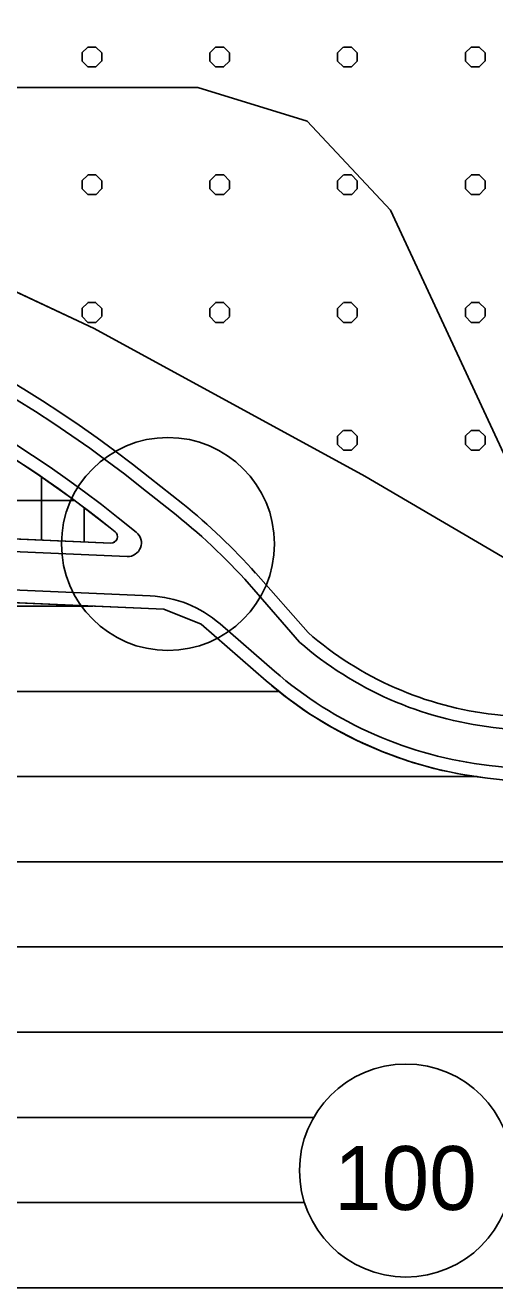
# Model space of a CAD drawing. Extents: x 427903 to 430077, y 4477233 to 4480385.
# Drawn here: x 429017.2 to 429127.4, y 4478826.8 to 4479123.1 of the extents above; entities that cross this region are included whole.
import ezdxf

# ---------------------------------------------------------------- set-up
doc = ezdxf.new("R2010")
doc.units = 0
for name, color, linetype in [('ADAKENARI', 7, 'Continuous'), ('KALDIRIM', 7, 'Continuous'), ('KD_KAV_DA', 7, 'Continuous'), ('PL_K_TALI_IS_MRK', 7, 'Continuous'), ('PL_KA_TARIM_OZEL', 7, 'Continuous'), ('PL_KON_ONE_100', 7, 'Continuous'), ('rezerv yapı alan', 7, 'Continuous'), ('SM_DAIRE', 7, 'Continuous'), ('SM_TAKS', 7, 'Continuous'), ('TR_AZYOGUNKONUT', 7, 'Continuous'), ('TR_OZELMAHSUL', 7, 'Continuous'), ('TR_TALIISMERK', 7, 'Continuous')]:
    doc.layers.add(name, color=color, linetype=linetype)

msp = doc.modelspace()

# ---------------------------------------------------------------- linework, layer by layer
at = {"layer": 'ADAKENARI'}
for p, q in [((428992.56, 4479071.13), (429033.41, 4479051.94)), ((429033.41, 4479051.94), (429096.95, 4479017.28)), ((429054.21, 4479010.76), (429046.48, 4479016.91)), ((429096.95, 4479017.28), (429125.65, 4479000.49)), ((429037.32, 4479001.59), (428951.02, 4479005.37)), ((429037.14, 4479005.18), (429038.31, 4479004.25)), ((429125.65, 4479000.49), (429154.73, 4478983.37)), ((429083.6, 4478980.58), (429071.31, 4478994.5)), ((428941.39, 4478990.78), (429049.73, 4478986.03)), ((429049.73, 4478986.03), (429058.49, 4478982.53)), ((429058.49, 4478982.53), (429073.75, 4478969.26)), ((429125.75, 4478946.4), (429168.82, 4478941.52))]:
    msp.add_line(p, q, dxfattribs=at)
for centre, radius, start, end in [((428857.96, 4478780.17), 302.64, 51.4698, 82.6888), ((428857.96, 4478780.17), 287.64, 51.4698, 70.6965), ((428970.23, 4478905.31), 134.8, 41.4256, 51.4698), ((429037.38, 4479003.08), 1.49, 267.4886, 51.4698), ((429136.51, 4479041.43), 80.64, 228.9909, 263.5412), ((429136.51, 4479041.43), 95.64, 228.9909, 263.5412)]:
    msp.add_arc(centre, radius, start, end, dxfattribs=at)
at = {"layer": 'KALDIRIM'}
for p, q in [((429044.61, 4479014.57), (429052.62, 4479008.19)), ((429039.01, 4479007.53), (429043.28, 4479004.12)), ((428941.91, 4479002.77), (429041.15, 4478998.42)), ((428941.52, 4478993.78), (429046.57, 4478989.17)), ((429070.85, 4478990.72), (429081.63, 4478978.32)), ((429062.94, 4478982.64), (429075.72, 4478971.52)), ((429127.1, 4478958.32), (429170.17, 4478953.45)), ((429126.09, 4478949.38), (429169.16, 4478944.5))]:
    msp.add_line(p, q, dxfattribs=at)
for centre, radius, start, end in [((428857.96, 4478780.17), 299.64, 51.4698, 82.6888), ((428857.96, 4478780.17), 290.64, 51.4698, 82.6888), ((428966.61, 4478900.17), 138.08, 40.9764, 51.4698), ((429041.29, 4479001.62), 3.2, 267.4886, 51.4698), ((429045.4, 4478962.47), 26.73, 48.9909, 87.4886), ((429136.51, 4479041.43), 83.64, 228.9909, 263.5412), ((429136.51, 4479041.43), 92.64, 228.9909, 263.5412)]:
    msp.add_arc(centre, radius, start, end, dxfattribs=at)
at = {"layer": 'KD_KAV_DA'}
msp.add_circle((429050.72, 4479001.37), 25, dxfattribs=at)
at = {"layer": 'PL_K_TALI_IS_MRK'}
msp.add_lwpolyline([(428951.02, 4479005.37), (428953.05, 4479051.63), (428963.1, 4479047.9), (428973.01, 4479043.8), (428982.75, 4479039.32), (428992.33, 4479034.49), (429001.71, 4479029.31), (429010.9, 4479023.77), (429019.88, 4479017.9), (429028.63, 4479011.7), (429037.14, 4479005.18), (429038.31, 4479004.25), (429038.63, 4479003.9), (429038.82, 4479003.48), (429038.87, 4479003.01), (429038.78, 4479002.56), (429038.55, 4479002.15), (429038.2, 4479001.83), (429037.78, 4479001.64), (429037.32, 4479001.59)], close=True, dxfattribs=at)
at = {"layer": 'PL_KA_TARIM_OZEL'}
msp.add_lwpolyline([(428824.34, 4479143.92), (428857.92, 4479130.08), (428947.92, 4479091.06), (428992.56, 4479071.13), (429033.41, 4479051.94), (429096.95, 4479017.28), (429125.65, 4479000.49), (429154.73, 4478983.37), (429181.58, 4478967.7), (429185.17, 4478965.6)], dxfattribs=at)
at = {"layer": 'PL_KON_ONE_100'}
for points in [[(429185.17, 4478965.6), (429181.58, 4478967.7), (429154.73, 4478983.37), (429125.65, 4479000.49), (429096.95, 4479017.28), (429033.41, 4479051.94), (428992.56, 4479071.13), (428947.92, 4479091.06), (428857.92, 4479130.08), (428824.34, 4479143.92)], [(429046.48, 4479016.91), (429054.21, 4479010.76)], [(429071.31, 4478994.5), (429083.6, 4478980.58)], [(428941.39, 4478990.78), (429049.73, 4478986.03), (429058.49, 4478982.53), (429073.75, 4478969.26), (429078.73, 4478965.22), (429083.96, 4478961.52), (429089.43, 4478958.18), (429095.11, 4478955.22), (429100.97, 4478952.64), (429106.99, 4478950.46), (429113.15, 4478948.69), (429119.41, 4478947.33), (429125.75, 4478946.4), (429168.82, 4478941.52)], [(429127.44, 4478961.3), (429170.51, 4478956.43)]]:
    msp.add_lwpolyline(points, dxfattribs=at)
for centre, radius, start, end in [((428857.96, 4478780.17), 302.64, 51.4698, 82.6888), ((428970.23, 4478905.31), 134.8, 41.4256, 51.4698), ((429136.51, 4479041.43), 80.64, 228.9909, 263.5412)]:
    msp.add_arc(centre, radius, start, end, dxfattribs=at)
at = {"layer": 'rezerv yapı alan'}
for p, q in [((428942.46, 4479108.55), (429057.71, 4479108.55)), ((429057.71, 4479108.55), (429083.4, 4479100.66)), ((429083.4, 4479100.66), (429102.93, 4479079.75)), ((429102.93, 4479079.75), (429129.55, 4479022.57))]:
    msp.add_line(p, q, dxfattribs=at)
msp.add_lwpolyline([(427921.98, 4479290.57), (427971.55, 4479260.72), (427987.38, 4479256.4), (428128.47, 4479257.63), (428368.56, 4479183.35), (428552.54, 4479194.57), (428656.99, 4479201.54), (428694.28, 4479196.96), (428778.69, 4479177.41), (428853.9, 4479147.32), (428942.46, 4479108.55), (429057.71, 4479108.55), (429083.4, 4479100.66), (429102.93, 4479079.75), (429129.55, 4479022.57), (429151, 4479001.12), (429217.97, 4478963.3), (429343.9, 4478891.1), (429611.87, 4478938.66), (429782.06, 4478938.49), (429965.11, 4478882.46), (430027.68, 4478900.91), (430040.04, 4478910.67)], dxfattribs=at)
at = {"layer": 'SM_DAIRE'}
msp.add_circle((429106.6, 4478854.28), 25, dxfattribs=at)
at = {"layer": 'TR_AZYOGUNKONUT'}
for p, q in [((428882.74, 4478986.76), (429033.1, 4478986.76)), ((428830.76, 4478966.76), (429076.83, 4478966.76)), ((428831.29, 4478946.76), (429123.3, 4478946.76)), ((428831.83, 4478926.76), (429212.28, 4478926.76)), ((428832.36, 4478906.76), (429237.53, 4478906.76)), ((428832.89, 4478886.76), (429258.66, 4478886.76)), ((428833.43, 4478866.76), (429084.93, 4478866.76)), ((428968.74, 4478846.76), (429082.75, 4478846.76)), ((428976.56, 4478826.76), (429289.71, 4478826.76))]:
    msp.add_line(p, q, dxfattribs=at)
for points in [[(429185.17, 4478965.6), (429181.58, 4478967.7), (429154.73, 4478983.37), (429125.65, 4479000.49), (429096.95, 4479017.28), (429033.41, 4479051.94), (428992.56, 4479071.13), (428947.92, 4479091.06), (428857.92, 4479130.08), (428824.34, 4479143.92)], [(429046.48, 4479016.91), (429054.21, 4479010.76)], [(429071.31, 4478994.5), (429083.6, 4478980.58)]]:
    msp.add_lwpolyline(points, dxfattribs=at)
for centre, radius, start, end in [((428857.96, 4478780.17), 302.64, 51.4698, 82.6888), ((428970.23, 4478905.31), 134.8, 41.4256, 51.4698), ((429136.51, 4479041.43), 80.64, 228.9909, 263.5412)]:
    msp.add_arc(centre, radius, start, end, dxfattribs=at)
at = {"layer": 'TR_OZELMAHSUL'}
for p, q in [((429030.52, 4479116.64), (429031.87, 4479117.99)), ((429031.9, 4479118.02), (429033.82, 4479118.02)), ((429035.17, 4479116.65), (429033.81, 4479118.01)), ((429060.51, 4479116.64), (429061.87, 4479117.99)), ((429061.9, 4479118.02), (429063.82, 4479118.02)), ((429065.17, 4479116.65), (429063.81, 4479118.01)), ((429090.51, 4479116.64), (429091.87, 4479117.99)), ((429091.9, 4479118.02), (429093.82, 4479118.02)), ((429095.17, 4479116.65), (429093.81, 4479118.01)), ((429120.51, 4479116.64), (429121.87, 4479117.99)), ((429121.9, 4479118.02), (429123.82, 4479118.02)), ((429125.17, 4479116.65), (429123.81, 4479118.01)), ((429030.54, 4479114.75), (429030.54, 4479116.66)), ((429031.9, 4479113.38), (429030.54, 4479114.74)), ((429033.79, 4479113.37), (429035.14, 4479114.72)), ((429035.17, 4479114.75), (429035.17, 4479116.66)), ((429060.54, 4479114.75), (429060.54, 4479116.66)), ((429061.9, 4479113.38), (429060.54, 4479114.74)), ((429063.78, 4479113.37), (429065.14, 4479114.72)), ((429065.17, 4479114.75), (429065.17, 4479116.66)), ((429090.54, 4479114.75), (429090.54, 4479116.66)), ((429091.9, 4479113.38), (429090.54, 4479114.74)), ((429093.78, 4479113.37), (429095.14, 4479114.72)), ((429095.17, 4479114.75), (429095.17, 4479116.66)), ((429120.54, 4479114.75), (429120.54, 4479116.66)), ((429121.9, 4479113.38), (429120.54, 4479114.74)), ((429123.78, 4479113.37), (429125.14, 4479114.72)), ((429125.17, 4479114.75), (429125.17, 4479116.66)), ((429031.9, 4479113.39), (429033.82, 4479113.39)), ((429061.9, 4479113.39), (429063.82, 4479113.39)), ((429091.9, 4479113.39), (429093.82, 4479113.39)), ((429121.9, 4479113.39), (429123.82, 4479113.39)), ((429030.52, 4479086.64), (429031.87, 4479087.99)), ((429031.9, 4479088.02), (429033.82, 4479088.02)), ((429035.17, 4479086.65), (429033.81, 4479088.01)), ((429060.51, 4479086.64), (429061.87, 4479087.99)), ((429061.9, 4479088.02), (429063.82, 4479088.02)), ((429065.17, 4479086.65), (429063.81, 4479088.01)), ((429090.51, 4479086.64), (429091.87, 4479087.99)), ((429091.9, 4479088.02), (429093.82, 4479088.02)), ((429095.17, 4479086.65), (429093.81, 4479088.01)), ((429120.51, 4479086.64), (429121.87, 4479087.99)), ((429121.9, 4479088.02), (429123.82, 4479088.02)), ((429125.17, 4479086.65), (429123.81, 4479088.01)), ((429030.54, 4479084.75), (429030.54, 4479086.66)), ((429035.17, 4479084.75), (429035.17, 4479086.66)), ((429060.54, 4479084.75), (429060.54, 4479086.66)), ((429065.17, 4479084.75), (429065.17, 4479086.66)), ((429090.54, 4479084.75), (429090.54, 4479086.66)), ((429095.17, 4479084.75), (429095.17, 4479086.66)), ((429120.54, 4479084.75), (429120.54, 4479086.66)), ((429125.17, 4479084.75), (429125.17, 4479086.66)), ((429031.9, 4479083.38), (429030.54, 4479084.74)), ((429031.9, 4479083.39), (429033.82, 4479083.39)), ((429033.79, 4479083.37), (429035.14, 4479084.72)), ((429061.9, 4479083.38), (429060.54, 4479084.74)), ((429061.9, 4479083.39), (429063.82, 4479083.39)), ((429063.78, 4479083.37), (429065.14, 4479084.72)), ((429091.9, 4479083.38), (429090.54, 4479084.74)), ((429091.9, 4479083.39), (429093.82, 4479083.39)), ((429093.78, 4479083.37), (429095.14, 4479084.72)), ((429121.9, 4479083.38), (429120.54, 4479084.74)), ((429121.9, 4479083.39), (429123.82, 4479083.39)), ((429123.78, 4479083.37), (429125.14, 4479084.72)), ((429030.52, 4479056.64), (429031.87, 4479057.99)), ((429030.54, 4479054.75), (429030.54, 4479056.66)), ((429031.9, 4479058.02), (429033.82, 4479058.02)), ((429035.17, 4479056.66), (429033.81, 4479058.01)), ((429035.17, 4479054.75), (429035.17, 4479056.66)), ((429060.51, 4479056.64), (429061.87, 4479057.99)), ((429060.54, 4479054.75), (429060.54, 4479056.66)), ((429061.9, 4479058.02), (429063.82, 4479058.02)), ((429065.17, 4479056.66), (429063.81, 4479058.01)), ((429065.17, 4479054.75), (429065.17, 4479056.66)), ((429090.51, 4479056.64), (429091.87, 4479057.99)), ((429090.54, 4479054.75), (429090.54, 4479056.66)), ((429091.9, 4479058.02), (429093.82, 4479058.02)), ((429095.17, 4479056.66), (429093.81, 4479058.01)), ((429095.17, 4479054.75), (429095.17, 4479056.66)), ((429120.51, 4479056.64), (429121.87, 4479057.99)), ((429120.54, 4479054.75), (429120.54, 4479056.66)), ((429121.9, 4479058.02), (429123.82, 4479058.02)), ((429125.17, 4479056.66), (429123.81, 4479058.01)), ((429125.17, 4479054.75), (429125.17, 4479056.66)), ((429031.9, 4479053.39), (429030.54, 4479054.74)), ((429031.9, 4479053.39), (429033.82, 4479053.39)), ((429033.79, 4479053.37), (429035.14, 4479054.72)), ((429061.9, 4479053.39), (429060.54, 4479054.74)), ((429061.9, 4479053.39), (429063.82, 4479053.39)), ((429063.78, 4479053.37), (429065.14, 4479054.72)), ((429091.9, 4479053.39), (429090.54, 4479054.74)), ((429091.9, 4479053.39), (429093.82, 4479053.39)), ((429093.78, 4479053.37), (429095.14, 4479054.72)), ((429121.9, 4479053.39), (429120.54, 4479054.74)), ((429121.9, 4479053.39), (429123.82, 4479053.39)), ((429123.78, 4479053.37), (429125.14, 4479054.72)), ((429090.51, 4479026.64), (429091.87, 4479027.99)), ((429090.54, 4479024.75), (429090.54, 4479026.66)), ((429091.9, 4479028.02), (429093.82, 4479028.02)), ((429095.17, 4479026.66), (429093.81, 4479028.01)), ((429095.17, 4479024.75), (429095.17, 4479026.66)), ((429120.51, 4479026.64), (429121.87, 4479027.99)), ((429120.54, 4479024.75), (429120.54, 4479026.66)), ((429121.9, 4479028.02), (429123.82, 4479028.02)), ((429125.16, 4479026.66), (429123.81, 4479028.01)), ((429125.17, 4479024.75), (429125.17, 4479026.66)), ((429091.9, 4479023.39), (429090.54, 4479024.74)), ((429091.9, 4479023.39), (429093.82, 4479023.39)), ((429093.78, 4479023.37), (429095.14, 4479024.72)), ((429121.89, 4479023.39), (429120.54, 4479024.74)), ((429121.9, 4479023.39), (429123.82, 4479023.39)), ((429123.78, 4479023.37), (429125.14, 4479024.72))]:
    msp.add_line(p, q, dxfattribs=at)
at = {"layer": 'TR_TALIISMERK'}
for p, q in [((429021.02, 4479002.3), (429021.02, 4479017.1)), ((428951.29, 4479011.59), (429028.78, 4479011.59)), ((429031.02, 4479001.86), (429031.02, 4479009.87))]:
    msp.add_line(p, q, dxfattribs=at)

# ---------------------------------------------------------------- texts
at = {"layer": 'SM_TAKS'}
msp.add_text('100', height=15, dxfattribs=at).set_placement((429089.73, 4478845.02))

doc.saveas('drawing.dxf')
